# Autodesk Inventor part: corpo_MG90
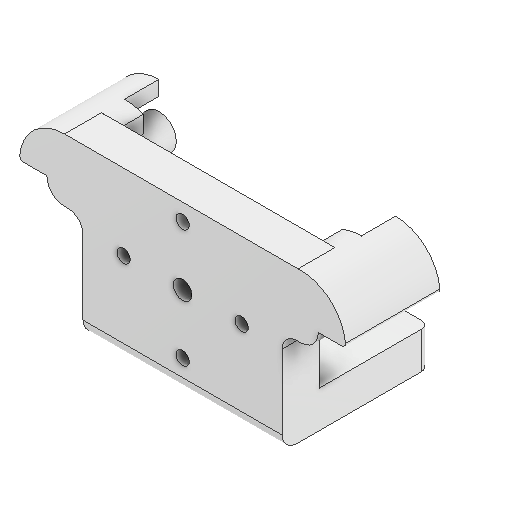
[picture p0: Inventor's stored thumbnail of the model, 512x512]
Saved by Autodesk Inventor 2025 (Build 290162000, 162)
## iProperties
Created: 2021-06
Part Number: corpo_MG90
Material: Plastica ABS
Document SubType Name: Modeling
Designer: Ryzen5700u
Density: 1.06 g/cm^3
Appearance: Default
Author: Ryzen5700u
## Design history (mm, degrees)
feature "Solido1"
node "Solido2"
